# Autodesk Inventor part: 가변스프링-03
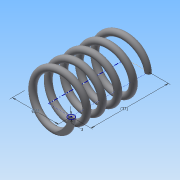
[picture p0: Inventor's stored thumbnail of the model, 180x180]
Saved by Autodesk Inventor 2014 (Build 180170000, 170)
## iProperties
Created: 2015-09
Part Number: 가변스프링-03
Material: 강철, 탄소
Document SubType Name: Modeling
Designer: study
Density: 7.87 g/cm^3
Appearance: 반연마
Mass: 18.7976 g
Surface Area: 32.4648 cm^2
Volume: 2.38851 cm^3
Author: study
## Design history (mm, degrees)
sketch "스케치1"
  geometry: L1 (0, 0)-(11, 0); L2 (11, 0)-(11, 29.043); L3 (11, 29.043)-(0, 29.043); L4 (0, 29.043)-(0, 0); C1 r 1.5 at (11, 0)
  constraints: 8 end point, 2 parallel, 1 centre point, 1 coincident, 1 horizontal, 1 perpendicular
  dimensions: "d0" = 29.04259 distance of L1.end L2.end (derived); "d1" = 22 diameter of L2 L4; "d2" = 3 diameter of C1
feature "코일1" sketch "스케치1" pitch "d3" = 10; turns "d5" = 5; dims "d4" = 29.04259 (= d0), "d6" = 0, angle "d7" = 90 deg, angle "d8" = 90 deg, "d9" = 0, "d10" = 0
node "작업 평면1"
sketch "스케치2"
  geometry: L1 (-12.5, 0)-(-9.5, 0) reference; 1 further point
  constraints: 1 horizontal alignment
extrude "돌출1" cut sketch "스케치2" stored distance "d12" = 10; taper "d13" = 0 deg
node "작업 평면2"
sketch "스케치3"
  geometry: L1 (-9.5, 0)-(-12.5, 0) reference; 1 further point
  constraints: 1 horizontal alignment
extrude "돌출2" cut sketch "스케치3" distance "d15" = 10; taper "d16" = 0 deg
node "솔리드1"
node "절단 모서리 투영1"
node "절단 모서리 투영2"
other parameters: "d11" = 0, "d14" = 29.04259 (= d0)
